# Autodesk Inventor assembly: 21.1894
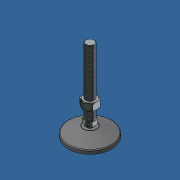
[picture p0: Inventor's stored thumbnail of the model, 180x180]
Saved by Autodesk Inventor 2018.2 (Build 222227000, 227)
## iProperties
Created: 2007-03
Part Number: 21.1894
Document SubType Name: Assembly
Designer: Andy Moles
Mass: 366.793 g
Surface Area: 346.812 cm^2
Volume: 104.278 cm^3
Density: 3.51745 g/cm^3
Description: LEVELING FOOT M16 80mm BASE
Author: Andy Moles
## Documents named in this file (5)
- Y:\INVENTOR LIBRARIES\PARTS LIBRARY\FEET WHEELS FLOOR FASTENING SUPPORTS\21.1894 LEVELING FOOT M16 80mm BASE.iam
- Y:\INVENTOR LIBRARIES\PARTS LIBRARY\FASTENING ELEMENTS\NUTS\21.1529 M16 HEX NUT.ipt
- Y:\INVENTOR LIBRARIES\PARTS LIBRARY\FEET WHEELS FLOOR FASTENING SUPPORTS\SUBCOMPONENTS\LEVELING FEET SUBCOMPONENTS\PAD 80mm PLASTIC.ipt
- Y:\INVENTOR LIBRARIES\PARTS LIBRARY\FEET WHEELS FLOOR FASTENING SUPPORTS\SUBCOMPONENTS\LEVELING FEET SUBCOMPONENTS\ANTI-SKID PAD 80mm.ipt
- Y:\INVENTOR LIBRARIES\PARTS LIBRARY\FEET WHEELS FLOOR FASTENING SUPPORTS\SUBCOMPONENTS\LEVELING FEET SUBCOMPONENTS\THREADED STUD 16mm SHORTER.ipt
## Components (4 placed, 4 different names)
1. ANTI-SKID PAD 80mm:1 — Insert:1
2. PAD 80mm PLASTIC:1 — Insert:1, Tangent:1, Mate:1
3. THREADED STUD 16mm SHORTER:1 — Tangent:1, Mate:1, Mate:2
4. 21.1529 M16 HEX NUT:1 — Mate:2
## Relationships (4: Mate 2, Insert 1, Tangent 1)
- Insert:1: ANTI-SKID PAD 80mm:1 ↔ PAD 80mm PLASTIC:1
- Tangent:1: PAD 80mm PLASTIC:1 ↔ THREADED STUD 16mm SHORTER:1
- Mate:1: PAD 80mm PLASTIC:1 ↔ THREADED STUD 16mm SHORTER:1
- Mate:2: THREADED STUD 16mm SHORTER:1 ↔ 21.1529 M16 HEX NUT:1
